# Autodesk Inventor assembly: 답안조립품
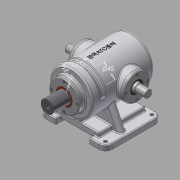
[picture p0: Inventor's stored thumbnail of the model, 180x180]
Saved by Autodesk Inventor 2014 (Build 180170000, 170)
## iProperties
Created: 2015-10
Part Number: 답안조립품
Document SubType Name: Assembly
Designer: youjin12
Author: youjin12
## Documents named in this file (13)
- C:\Users\youjin12\Desktop\351019V1010\답안조립품.iam
- C:\Users\youjin12\Desktop\351019V1010\본체.ipt
- C:\Users\youjin12\Desktop\351019V1010\슬라이드 커버.ipt
- C:\Users\youjin12\Desktop\351019V1010\부시.ipt
- C:\Users\youjin12\Desktop\351019V1010\베어링 6205.ipt
- 베어링 6205.ipt
- C:\Users\youjin12\Desktop\351019V1010\편심축.ipt
- C:\Users\youjin12\Desktop\351019V1010\축 커버.ipt
- C:\Users\youjin12\Desktop\351019V1010\가변스프링.ipt
- C:\Users\youjin12\Desktop\351019V1010\M4x0.7.ipt
- C:\Users\youjin12\Desktop\351019V1010\슬라이드.ipt
- C:\Users\youjin12\Desktop\351019V1010\오일실.ipt
- 오일실.ipt
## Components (13 placed, 2 different names)
1. 가변스프링:1
2. M4x0.7:3
3. M4x0.7:4
4. M4x0.7:5
5. M4x0.7:6
6. M4x0.7:2
7. M4x0.7:7
8. M4x0.7:8
9. M4x0.7:9
10. M4x0.7:1
11. M4x0.7:10
12. M4x0.7:11
13. M4x0.7:12
